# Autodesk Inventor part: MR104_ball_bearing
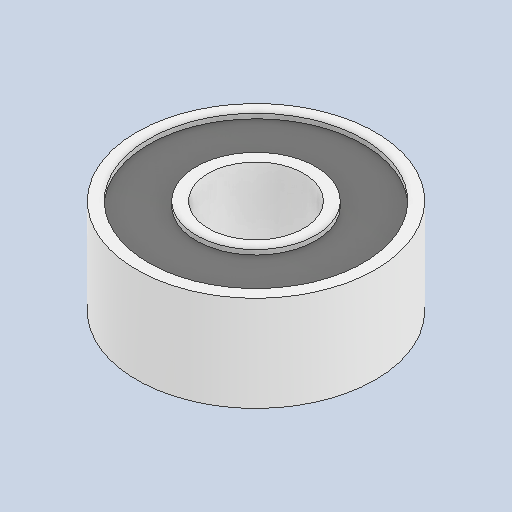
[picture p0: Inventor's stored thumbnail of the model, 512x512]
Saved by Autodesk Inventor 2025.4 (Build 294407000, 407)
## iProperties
Created: 2026-09
Part Number: MR104_ball_bearing
Material: Generic
Document SubType Name: Modeling
Designer: AdminForWorker
Density: 1 g/cm^3
Appearance: Default
Title: MR104_ball_bearing v1
Author: AdminForWorker
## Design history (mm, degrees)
feature "Body1"
body "Solid1"
